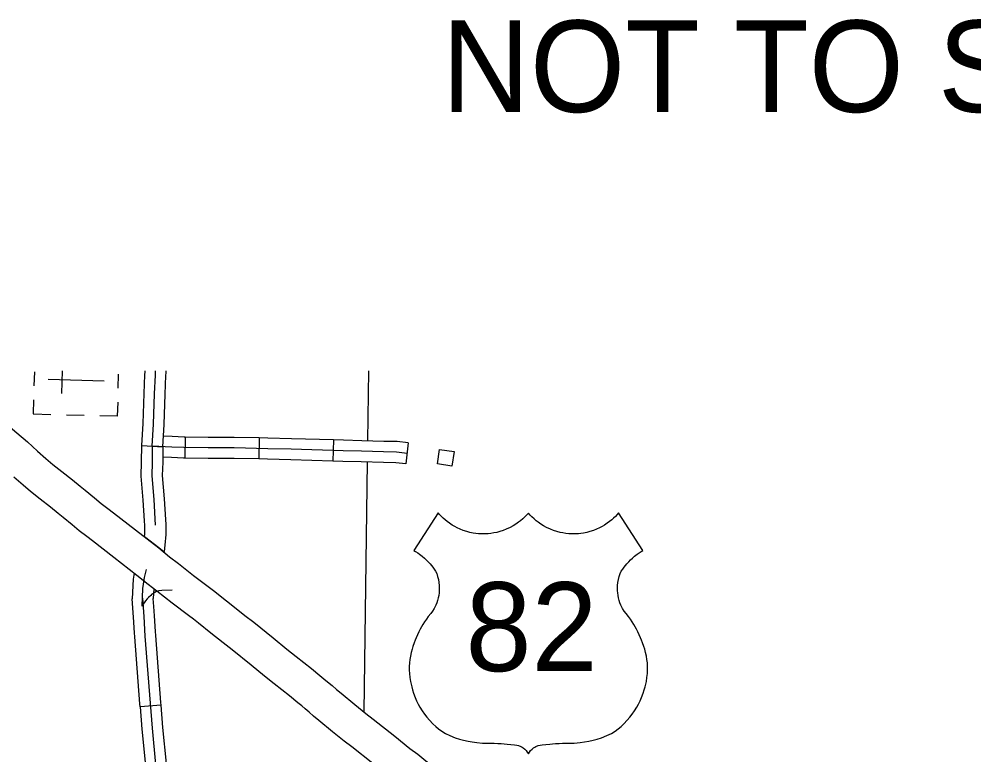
# Model space of a CAD drawing. Extents: x 61396 to 64680, y 55472 to 57605.
# Drawn here: x 62213.6 to 62426.4, y 56599.7 to 56763.6 of the extents above; entities that cross this region are included whole.
import ezdxf

# ---------------------------------------------------------------- set-up
doc = ezdxf.new("R2010")
doc.units = 0
for name, color, linetype in [('15', 7, 'Continuous'), ('22', 7, 'Continuous'), ('31', 7, 'Continuous'), ('32', 7, 'Continuous'), ('5', 7, 'Continuous'), ('56', 7, 'Continuous'), ('57', 7, 'Continuous'), ('Default', 7, 'Continuous')]:
    doc.layers.add(name, color=color, linetype=linetype)

msp = doc.modelspace()

# ---------------------------------------------------------------- linework, layer by layer
at = {"layer": '15'}
for points in [[(62210.76, 56673.47), (62215.48, 56669.46), (62217.7, 56667.39), (62219.61, 56665.74), (62221.14, 56664.44), (62223.17, 56662.82), (62225.5, 56661.01), (62227.24, 56659.57), (62228.35, 56658.7), (62230.46, 56656.95), (62231.94, 56655.71), (62233.38, 56654.6), (62234.7, 56653.64), (62239.57, 56649.89), (62244.75, 56645.82), (62247.18, 56643.87), (62249.15, 56642.37), (62252.49, 56639.69), (62256.07, 56637.03), (62257.24, 56636.14), (62258.47, 56635.19), (62261.28, 56632.95), (62263.96, 56630.78), (62265.92, 56629.26), (62270.26, 56625.8), (62273.32, 56623.31), (62275.35, 56621.61), (62278.81, 56618.95), (62280.67, 56617.4), (62281.58, 56616.68), (62282.37, 56616.01), (62283.38, 56615.19), (62284.36, 56614.29), (62285.4, 56613.45), (62288.44, 56610.95), (62290.92, 56608.96), (62292.57, 56607.7), (62297.34, 56603.87), (62300.7, 56601.18), (62302.51, 56599.92), (62306, 56596.96)], [(62292.45, 56597.78), (62287.76, 56601.55), (62286.11, 56602.8), (62283.51, 56604.88), (62280.45, 56607.4), (62279.27, 56608.36), (62278.28, 56609.26), (62277.38, 56609.99), (62276.61, 56610.64), (62275.72, 56611.35), (62273.93, 56612.85), (62270.45, 56615.52), (62268.35, 56617.29), (62265.36, 56619.71), (62261.09, 56623.12), (62259.11, 56624.65), (62256.39, 56626.86), (62253.64, 56629.04), (62252.48, 56629.95), (62251.37, 56630.79), (62247.71, 56633.51), (62244.35, 56636.21), (62242.37, 56637.71), (62239.89, 56639.71), (62234.78, 56643.72), (62230.02, 56647.38), (62228.7, 56648.34), (62227.04, 56649.62), (62225.46, 56650.95), (62223.45, 56652.61), (62222.34, 56653.48), (62220.61, 56654.91), (62218.33, 56656.69), (62216.17, 56658.41), (62214.53, 56659.81), (62212.49, 56661.57)]]:
    msp.add_lwpolyline(points, dxfattribs=at)
at = {"layer": '22'}
for points in [[(62327.14, 56653.59), (62326.73, 56653.13), (62326.33, 56652.72), (62325.89, 56652.3), (62325.4, 56651.89), (62324.94, 56651.53), (62324.37, 56651.13), (62323.77, 56650.76), (62323.08, 56650.38), (62322.2, 56649.97), (62321.53, 56649.71), (62320.77, 56649.47), (62320.08, 56649.28), (62319.44, 56649.15), (62318.76, 56649.05), (62318.14, 56648.98), (62317.29, 56648.94), (62316.6, 56648.95), (62316, 56648.99), (62315.43, 56649.05), (62314.85, 56649.14), (62314.12, 56649.29), (62313.44, 56649.46), (62312.62, 56649.73), (62311.92, 56650.01), (62311.29, 56650.3), (62310.71, 56650.6), (62310.18, 56650.91), (62309.58, 56651.31), (62309.03, 56651.71), (62308.56, 56652.09), (62308.16, 56652.45), (62307.75, 56652.84), (62307.35, 56653.26), (62307.03, 56653.63), (62301.62, 56645.27), (62302.01, 56645.04), (62302.47, 56644.74), (62302.9, 56644.43), (62303.48, 56643.97), (62303.95, 56643.57), (62304.36, 56643.19), (62304.78, 56642.76), (62305.21, 56642.29), (62305.51, 56641.92), (62305.82, 56641.52), (62306.13, 56641.09), (62306.43, 56640.64), (62306.7, 56640.11), (62306.91, 56639.46), (62307.07, 56638.81), (62307.19, 56638.12), (62307.26, 56637.48), (62307.28, 56636.86), (62307.26, 56636.28), (62307.22, 56635.82), (62307.15, 56635.25), (62307.04, 56634.71), (62306.89, 56634.13), (62306.73, 56633.62), (62306.51, 56633.05), (62306.15, 56632.31), (62305.79, 56631.74), (62305.36, 56631.21), (62304.83, 56630.53), (62304.4, 56629.94), (62304, 56629.34), (62303.63, 56628.76), (62303.32, 56628.23), (62303.05, 56627.74), (62302.74, 56627.16), (62302.42, 56626.48), (62302.12, 56625.81), (62301.92, 56625.31), (62301.68, 56624.67), (62301.42, 56623.9), (62301.21, 56623.25), (62301.01, 56622.54), (62300.83, 56621.72), (62300.71, 56620.99), (62300.62, 56620.23), (62300.57, 56619.39), (62300.57, 56618.61), (62300.61, 56617.85), (62300.7, 56616.95), (62300.84, 56616.1), (62300.98, 56615.46), (62301.13, 56614.89), (62301.31, 56614.25), (62301.56, 56613.46), (62301.92, 56612.5), (62302.22, 56611.79), (62302.58, 56611.06), (62302.97, 56610.34), (62303.48, 56609.52), (62304.01, 56608.77), (62304.52, 56608.11), (62305.1, 56607.44), (62305.84, 56606.66), (62306.48, 56606.07), (62307.13, 56605.52)], [(62347.14, 56605.52), (62347.79, 56606.07), (62348.43, 56606.66), (62349.18, 56607.44), (62349.76, 56608.11), (62350.27, 56608.77), (62350.79, 56609.52), (62351.3, 56610.34), (62351.69, 56611.06), (62352.05, 56611.79), (62352.36, 56612.5), (62352.72, 56613.46), (62352.96, 56614.25), (62353.15, 56614.89), (62353.3, 56615.46), (62353.44, 56616.1), (62353.57, 56616.95), (62353.67, 56617.85), (62353.7, 56618.61), (62353.7, 56619.39), (62353.65, 56620.23), (62353.56, 56620.99), (62353.44, 56621.72), (62353.26, 56622.54), (62353.06, 56623.25), (62352.86, 56623.9), (62352.59, 56624.67), (62352.35, 56625.31), (62352.15, 56625.81), (62351.86, 56626.48), (62351.53, 56627.16), (62351.22, 56627.74), (62350.95, 56628.23), (62350.64, 56628.76), (62350.28, 56629.34), (62349.87, 56629.94), (62349.44, 56630.53), (62348.92, 56631.21), (62348.48, 56631.74), (62348.12, 56632.31), (62347.77, 56633.05), (62347.55, 56633.62), (62347.38, 56634.13), (62347.23, 56634.71), (62347.13, 56635.25), (62347.05, 56635.82), (62347.01, 56636.28), (62347, 56636.86), (62347.02, 56637.48), (62347.08, 56638.12), (62347.2, 56638.81), (62347.36, 56639.46), (62347.57, 56640.11), (62347.85, 56640.64), (62348.15, 56641.09), (62348.46, 56641.52), (62348.76, 56641.92), (62349.07, 56642.29), (62349.5, 56642.76), (62349.91, 56643.19), (62350.33, 56643.57), (62350.79, 56643.97), (62351.37, 56644.43), (62351.81, 56644.74), (62352.27, 56645.04), (62352.65, 56645.27), (62347.24, 56653.63), (62346.92, 56653.26), (62346.52, 56652.84), (62346.12, 56652.45), (62345.72, 56652.09), (62345.24, 56651.71), (62344.7, 56651.31), (62344.1, 56650.91), (62343.56, 56650.6), (62342.98, 56650.3), (62342.35, 56650.01), (62341.65, 56649.73), (62340.83, 56649.46), (62340.16, 56649.29), (62339.43, 56649.14), (62338.85, 56649.05), (62338.27, 56648.99), (62337.67, 56648.95), (62336.98, 56648.94), (62336.13, 56648.98), (62335.51, 56649.05), (62334.84, 56649.15), (62334.2, 56649.28), (62333.5, 56649.47), (62332.74, 56649.71), (62332.07, 56649.97), (62331.2, 56650.38), (62330.51, 56650.76), (62329.9, 56651.13), (62329.34, 56651.53), (62328.87, 56651.89), (62328.39, 56652.3), (62327.94, 56652.72), (62327.55, 56653.13), (62327.14, 56653.59)], [(62307.13, 56605.52), (62307.81, 56605.01), (62308.63, 56604.48), (62309.65, 56604.02), (62310.85, 56603.56), (62311.82, 56603.24), (62312.7, 56603), (62313.7, 56602.77), (62314.63, 56602.6), (62315.64, 56602.46), (62316.9, 56602.35), (62317.87, 56602.32), (62318.7, 56602.32), (62319.5, 56602.31), (62320.31, 56602.29), (62321.07, 56602.25), (62321.74, 56602.21), (62322.39, 56602.15), (62323.23, 56602.06), (62324.06, 56601.96), (62324.55, 56601.89), (62324.96, 56601.81), (62325.45, 56601.61), (62325.73, 56601.45), (62325.98, 56601.29), (62326.31, 56601.02), (62326.64, 56600.69), (62326.9, 56600.35), (62327.14, 56599.96)], [(62327.14, 56599.96), (62327.38, 56600.35), (62327.64, 56600.69), (62327.96, 56601.02), (62328.3, 56601.29), (62328.54, 56601.45), (62328.83, 56601.61), (62329.32, 56601.81), (62329.73, 56601.89), (62330.22, 56601.96), (62331.04, 56602.06), (62331.88, 56602.15), (62332.54, 56602.21), (62333.2, 56602.25), (62333.97, 56602.29), (62334.77, 56602.31), (62335.58, 56602.32), (62336.41, 56602.32), (62337.37, 56602.35), (62338.64, 56602.46), (62339.64, 56602.6), (62340.58, 56602.77), (62341.57, 56603), (62342.45, 56603.24), (62343.43, 56603.56), (62344.62, 56604.02), (62345.65, 56604.48), (62346.46, 56605.01), (62347.14, 56605.52)]]:
    msp.add_lwpolyline(points, dxfattribs=at)
at = {"layer": '31'}
for p, q in [((62240.98, 56668.61), (62245.65, 56668.33)), ((62245.29, 56610.78), (62240.62, 56610.42))]:
    msp.add_line(p, q, dxfattribs=at)
for points in [[(62240.98, 56668.61), (62241.27, 56673.51), (62241.5, 56680.24), (62241.68, 56684.41), (62241.71, 56685.05)], [(62241.71, 56685.05), (62241.72, 56685.27)], [(62243.31, 56668.47), (62243.61, 56673.4), (62243.84, 56680.15), (62244.02, 56684.31), (62244.06, 56685.27)], [(62245.65, 56668.33), (62245.95, 56673.29), (62246.18, 56680.06), (62246.37, 56684.21), (62246.39, 56684.85)], [(62246.39, 56684.85), (62246.41, 56685.27)], [(62241.56, 56651.87), (62241.31, 56656.44), (62240.84, 56661.79), (62240.94, 56665), (62240.98, 56668.61)], [(62243.31, 56668.47), (62243.29, 56664.96), (62243.18, 56661.86), (62243.65, 56656.61), (62243.96, 56650.92)], [(62245.65, 56668.33), (62245.63, 56664.91), (62245.53, 56661.92), (62245.99, 56656.77), (62246.24, 56652.12)], [(62241.62, 56650.79), (62241.56, 56651.87)], [(62246.24, 56652.12), (62246.3, 56651.04)], [(62246.3, 56651.04), (62246.34, 56648.81), (62246.11, 56646.42), (62245.94, 56645.04), (62245.88, 56644.92), (62244.75, 56645.82), (62241.58, 56648.31)], [(62241.58, 56648.31), (62241.64, 56648.99), (62241.62, 56650.79)], [(62241.97, 56641.02), (62241.5, 56639.26), (62241.16, 56636.81), (62240.96, 56632.84)], [(62239.25, 56640.21), (62239.06, 56638.87), (62238.85, 56634.49)], [(62247.77, 56636.45), (62245.41, 56636.35), (62244.81, 56636.24), (62244.29, 56636.1), (62243.86, 56635.91), (62243.24, 56635.52), (62242.96, 56635.25), (62242.48, 56634.82), (62242.16, 56634.49), (62241.79, 56634.06), (62240.96, 56632.84)], [(62243.65, 56636.75), (62243.53, 56634.54)], [(62239.36, 56626.92), (62239.16, 56630.42), (62238.85, 56634.49)], [(62245.16, 56544.7), (62245.34, 56547.91), (62245.4, 56561.59), (62245.46, 56571.07), (62245.28, 56576.79), (62244.97, 56587), (62244.12, 56597.58), (62243.33, 56605.66), (62242.91, 56611.25), (62241.75, 56626.15), (62241.5, 56630.57), (62241.19, 56634.67)], [(62244.04, 56627.19), (62243.83, 56630.73), (62243.68, 56632.76), (62243.53, 56634.54)], [(62240.62, 56610.42), (62240.57, 56611.07), (62239.41, 56625.99), (62239.36, 56626.92)], [(62245.29, 56610.78), (62245.24, 56611.43), (62244.09, 56626.3), (62244.04, 56627.19)], [(62240.62, 56610.42), (62241, 56605.46), (62241.79, 56597.37), (62242.06, 56593.98)], [(62246.73, 56594.35), (62246.46, 56597.78), (62245.67, 56605.86), (62245.29, 56610.78)]]:
    msp.add_lwpolyline(points, dxfattribs=at)
at = {"layer": '32'}
for p, q in [((62250.66, 56670.52), (62250.57, 56665.83)), ((62267.16, 56670.31), (62267.07, 56665.63)), ((62283.68, 56669.87), (62283.54, 56665.18)), ((62300.36, 56669.21), (62299.81, 56664.55))]:
    msp.add_line(p, q, dxfattribs=at)
for points in [[(62250.66, 56670.52), (62250.41, 56670.52), (62247.76, 56670.65), (62245.8, 56670.72)], [(62267.16, 56670.31), (62261.6, 56670.42), (62255.78, 56670.42), (62250.66, 56670.52)], [(62300.09, 56666.88), (62297.74, 56667.16), (62294.86, 56667.2), (62289.94, 56667.35), (62285.84, 56667.45), (62274.27, 56667.8), (62269.05, 56667.93), (62261.58, 56668.08), (62255.76, 56668.08), (62250.33, 56668.18), (62247.66, 56668.3), (62243.31, 56668.47)], [(62283.68, 56669.87), (62274.34, 56670.15), (62269.1, 56670.27), (62267.16, 56670.31)], [(62300.36, 56669.21), (62297.89, 56669.5), (62294.92, 56669.55), (62290.01, 56669.7), (62285.91, 56669.8), (62283.68, 56669.87)], [(62250.57, 56665.83), (62250.26, 56665.84), (62247.56, 56665.96), (62245.64, 56666.03)], [(62267.07, 56665.63), (62261.56, 56665.74), (62255.74, 56665.74), (62250.57, 56665.83)], [(62283.54, 56665.18), (62274.21, 56665.46), (62269, 56665.59), (62267.07, 56665.63)], [(62299.81, 56664.55), (62297.58, 56664.81), (62294.81, 56664.86), (62289.88, 56665.01), (62285.78, 56665.11), (62283.54, 56665.18)]]:
    msp.add_lwpolyline(points, dxfattribs=at)
at = {"layer": '5'}
for points in [[(62291.51, 56685.27), (62291.3, 56669.66)], [(62291.23, 56664.97), (62290.45, 56609.32)]]:
    msp.add_lwpolyline(points, dxfattribs=at)
at = {"layer": '56'}
msp.add_lwpolyline([(62306.85, 56664.57), (62307.34, 56667.78), (62310.56, 56667.29), (62310.07, 56664.07)], close=True, dxfattribs=at)
at = {"layer": '57'}
for p, q in [((62217.04, 56685.07), (62216.95, 56681.95)), ((62220.12, 56683.41), (62232.61, 56683.06)), ((62223.15, 56680.19), (62223.29, 56685.27)), ((62226.36, 56683.23), (62226.36, 56683.23)), ((62226.36, 56683.23), (62226.36, 56683.23)), ((62235.69, 56681.43), (62235.78, 56684.55)), ((62224.22, 56675.48), (62228.13, 56675.37))]:
    msp.add_line(p, q, dxfattribs=at)
for points in [[(62216.86, 56678.81), (62216.78, 56675.68), (62220.68, 56675.57)], [(62235.61, 56678.29), (62235.52, 56675.16), (62231.61, 56675.27)]]:
    msp.add_lwpolyline(points, dxfattribs=at)

# ---------------------------------------------------------------- texts
at = {"layer": '22'}
msp.add_text('82', height=19.8, dxfattribs=at).set_placement((62313.11, 56618.38))
at = {"layer": 'Default'}
msp.add_text('NOT TO SCALE', height=20.4, dxfattribs=at).set_placement((62307.79, 56742.9))

doc.saveas('drawing.dxf')
